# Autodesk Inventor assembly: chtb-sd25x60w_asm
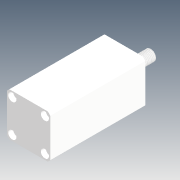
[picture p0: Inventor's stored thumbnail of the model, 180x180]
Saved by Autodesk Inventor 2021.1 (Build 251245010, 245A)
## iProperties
Company: Microsoft
Created: 2018-05
Part Number: chtb-sd25x60w_asm
Description: STEP AP214
Document SubType Name: Assembly
Designer: user
Title: chtb-sd25x60w_asm.STEP
Author: Windows
Revision Number: ÈÎºÎ
Sending System: SolidWorks 2015
Preprocessor: SwSTEP 2.0
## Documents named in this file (4)
- D:\Vault_2016\Projekty\Clamptek\Hydraulic\CHTB\CHTB-25\Inventor\chtb-sd25x60w\chtb-sd25x60w_asm.iam
- D:\Vault_2016\Projekty\Clamptek\Hydraulic\CHTB\CHTB-25\Inventor\chtb-sd25x60w\CHTB-25QG.ipt
- D:\Vault_2016\Projekty\Clamptek\Hydraulic\CHTB\CHTB-25\Inventor\chtb-sd25x60w\CHTB-SD25X60NBT.ipt
- D:\Vault_2016\Projekty\Clamptek\Hydraulic\CHTB\CHTB-25\Inventor\chtb-sd25x60w\CHTB-SD25X60WHSG.ipt
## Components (3 placed, 3 different names)
1. CHTB-25QG_1
2. CHTB-SD25X60NBT_2
3. CHTB-SD25X60WHSG_3
